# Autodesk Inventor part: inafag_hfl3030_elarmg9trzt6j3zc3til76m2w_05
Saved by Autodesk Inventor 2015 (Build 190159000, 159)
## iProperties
Company: TraceParts S.A.
Created: 2012-12
Part Number: inafag_hfl3030_elarmg9trzt6j3zc3til76m2w_05
Checked By: TraceParts S.A.
Catalog Web Link: www.traceparts.com
Document SubType Name: Modeling
Designer: TraceParts
Material: Generic
Density: 1 g/cm^3
Appearance: Default
Author: TraceParts
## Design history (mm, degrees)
feature "inafag_hfl3030_elarmg9trzt6j3zc3til76m2w"
body "Solid1"
